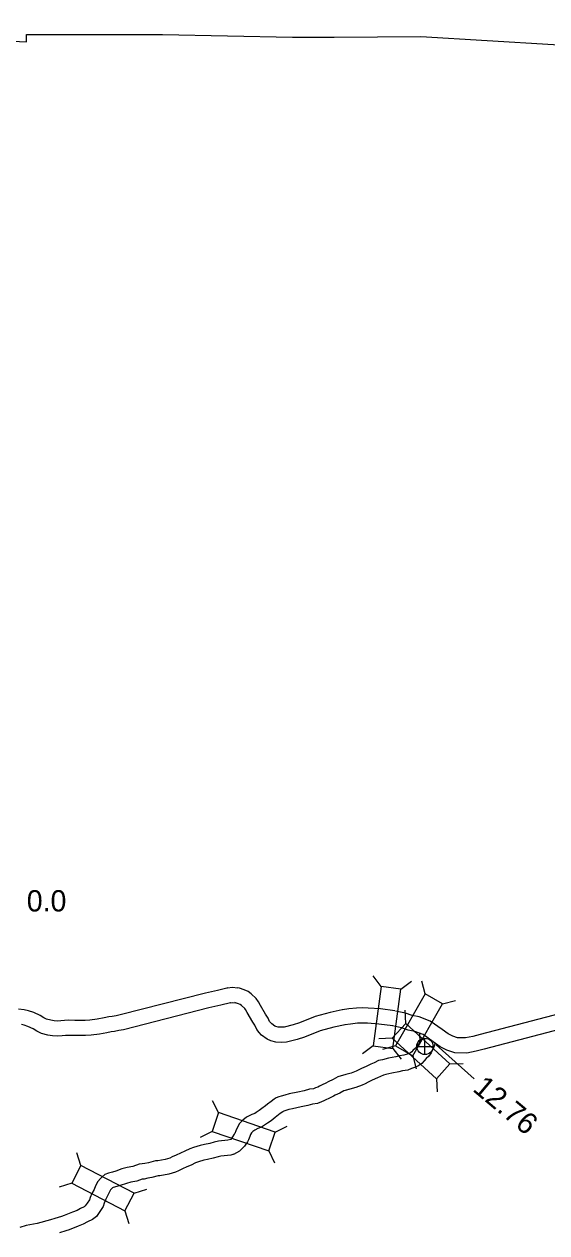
# Model space of a CAD drawing. Extents: x -939622 to -934245, y 1383184 to 1385301.
# Drawn here: x -936213.9 to -936182.8, y 1384317.3 to 1384389.2 of the extents above; entities that cross this region are included whole.
import ezdxf

# ---------------------------------------------------------------- set-up
doc = ezdxf.new("R2010")
doc.units = 0
for name, color, linetype in [('Level 10', 7, 'Continuous'), ('Level 2', 7, 'Continuous'), ('Level 20', 7, 'Continuous'), ('Level 25', 7, 'Continuous'), ('Level 26', 7, 'Continuous')]:
    doc.layers.add(name, color=color, linetype=linetype)

msp = doc.modelspace()

# ---------------------------------------------------------------- linework, layer by layer
at = {"layer": 'Level 10'}
for points in [[(-936201.82, 1384331.839), (-936201.866, 1384331.829), (-936202.427, 1384331.691), (-936203.146, 1384331.53), (-936208.214, 1384330.232), (-936208.445, 1384330.188), (-936208.692, 1384330.145), (-936208.889, 1384330.116), (-936209.171, 1384330.064), (-936209.59, 1384329.988), (-936210.023, 1384329.925), (-936210.302, 1384329.914), (-936210.655, 1384329.913), (-936210.918, 1384329.911), (-936211.259, 1384329.919), (-936211.527, 1384329.913), (-936211.743, 1384329.892), (-936211.968, 1384329.874), (-936212.138, 1384329.886), (-936212.332, 1384329.919), (-936212.587, 1384329.984), (-936212.75, 1384330.062), (-936212.971, 1384330.195), (-936213.357, 1384330.377), (-936213.662, 1384330.482), (-936213.922, 1384330.545), (-936214.261, 1384330.585)], [(-936201.82, 1384331.839), (-936201.532, 1384331.88), (-936201.237, 1384331.853)], [(-936195.013, 1384330.53), (-936195.714, 1384330.382), (-936196.608, 1384330.141), (-936197.556, 1384329.766), (-936197.931, 1384329.642), (-936198.454, 1384329.509), (-936198.619, 1384329.499), (-936198.815, 1384329.512), (-936198.962, 1384329.546), (-936199.01, 1384329.568), (-936199.2, 1384329.704), (-936199.259, 1384329.773), (-936199.322, 1384329.851), (-936199.418, 1384330.05), (-936199.561, 1384330.281), (-936199.873, 1384330.795), (-936199.977, 1384331.022), (-936200.126, 1384331.219), (-936200.425, 1384331.492), (-936200.603, 1384331.628), (-936200.836, 1384331.737), (-936201.121, 1384331.828), (-936201.237, 1384331.853)], [(-936174.729, 1384332.074), (-936175.041, 1384332.067), (-936175.524, 1384331.953), (-936176.172, 1384331.815), (-936176.86, 1384331.672), (-936186.804, 1384329.07), (-936187.241, 1384328.949), (-936187.674, 1384328.871), (-936188.153, 1384328.877), (-936188.428, 1384328.975), (-936188.71, 1384329.113), (-936189.068, 1384329.373), (-936189.778, 1384329.874), (-936190.439, 1384330.113), (-936190.842, 1384330.192), (-936191.235, 1384330.339), (-936191.835, 1384330.468)], [(-936201.638, 1384330.957), (-936201.659, 1384330.953), (-936202.221, 1384330.815), (-936202.936, 1384330.654), (-936208.017, 1384329.354), (-936208.283, 1384329.303), (-936208.549, 1384329.256), (-936208.741, 1384329.228), (-936209.009, 1384329.178), (-936209.445, 1384329.1), (-936209.939, 1384329.028), (-936210.283, 1384329.014), (-936210.649, 1384329.013), (-936210.925, 1384329.011), (-936211.26, 1384329.019), (-936211.472, 1384329.014), (-936211.663, 1384328.995), (-936211.964, 1384328.972), (-936212.244, 1384328.991), (-936212.519, 1384329.037), (-936212.894, 1384329.134), (-936213.177, 1384329.268), (-936213.396, 1384329.4), (-936213.697, 1384329.542), (-936213.915, 1384329.617), (-936214.081, 1384329.658)], [(-936201.674, 1384330.951), (-936201.509, 1384330.974), (-936201.346, 1384330.96)], [(-936194.826, 1384329.65), (-936195.503, 1384329.506), (-936196.324, 1384329.285), (-936197.249, 1384328.919), (-936197.679, 1384328.777), (-936198.315, 1384328.616), (-936198.623, 1384328.597), (-936198.948, 1384328.62), (-936199.252, 1384328.689), (-936199.463, 1384328.785), (-936199.811, 1384329.034), (-936199.951, 1384329.197), (-936200.089, 1384329.369), (-936200.208, 1384329.618), (-936200.328, 1384329.811), (-936200.668, 1384330.371), (-936200.754, 1384330.557), (-936200.794, 1384330.61), (-936201.003, 1384330.801), (-936201.073, 1384330.854), (-936201.165, 1384330.898), (-936201.355, 1384330.958), (-936201.402, 1384330.968)], [(-936174.707, 1384331.175), (-936174.925, 1384331.169), (-936175.326, 1384331.075), (-936175.987, 1384330.934), (-936176.655, 1384330.796), (-936186.57, 1384328.201), (-936187.041, 1384328.071), (-936187.6, 1384327.969), (-936188.313, 1384327.979), (-936188.778, 1384328.144), (-936189.177, 1384328.34), (-936189.592, 1384328.641), (-936190.198, 1384329.069), (-936190.68, 1384329.243), (-936191.088, 1384329.323), (-936191.489, 1384329.473), (-936192.025, 1384329.589)], [(-936191.87, 1384330.475), (-936192.729, 1384330.59), (-936193.457, 1384330.643), (-936193.771, 1384330.653), (-936194.163, 1384330.635), (-936194.616, 1384330.589), (-936194.984, 1384330.536)], [(-936191.989, 1384329.583), (-936192.822, 1384329.694), (-936193.503, 1384329.744), (-936193.764, 1384329.752), (-936194.097, 1384329.737), (-936194.505, 1384329.696), (-936194.855, 1384329.645)], [(-936190.415, 1384329.159), (-936190.417, 1384329.121), (-936190.41, 1384328.954), (-936190.384, 1384328.811), (-936190.371, 1384328.749), (-936190.371, 1384328.735), (-936190.391, 1384328.673), (-936190.434, 1384328.56), (-936190.487, 1384328.469), (-936190.559, 1384328.362), (-936190.655, 1384328.268), (-936190.796, 1384328.117), (-936190.863, 1384328.042), (-936190.951, 1384327.984), (-936191.033, 1384327.947), (-936191.193, 1384327.89), (-936191.34, 1384327.834), (-936191.596, 1384327.796), (-936191.823, 1384327.737), (-936192.25, 1384327.66), (-936192.618, 1384327.567), (-936192.839, 1384327.521), (-936193.114, 1384327.393), (-936193.3, 1384327.304), (-936193.587, 1384327.17), (-936193.858, 1384327.055), (-936194.06, 1384326.943), (-936194.175, 1384326.889), (-936194.48, 1384326.771), (-936194.789, 1384326.689), (-936194.985, 1384326.635)], [(-936189.482, 1384328.563), (-936189.54, 1384328.378), (-936189.619, 1384328.171), (-936189.724, 1384327.99), (-936189.864, 1384327.782), (-936190.011, 1384327.639), (-936190.131, 1384327.51), (-936190.271, 1384327.355), (-936190.516, 1384327.192), (-936190.697, 1384327.112), (-936190.882, 1384327.045), (-936191.111, 1384326.958), (-936191.417, 1384326.912), (-936191.632, 1384326.857), (-936192.06, 1384326.78), (-936192.414, 1384326.691), (-936192.553, 1384326.661), (-936192.73, 1384326.579), (-936192.914, 1384326.49), (-936193.222, 1384326.347), (-936193.464, 1384326.245), (-936193.649, 1384326.142), (-936193.819, 1384326.062), (-936194.201, 1384325.913), (-936194.555, 1384325.82), (-936194.747, 1384325.767)], [(-936194.795, 1384326.687), (-936195.266, 1384326.553), (-936195.552, 1384326.39), (-936195.847, 1384326.266), (-936195.979, 1384326.182), (-936196.197, 1384326.069), (-936196.35, 1384325.996), (-936196.459, 1384325.948), (-936196.595, 1384325.891), (-936196.71, 1384325.843), (-936196.952, 1384325.811), (-936197.261, 1384325.728), (-936197.642, 1384325.643), (-936198.162, 1384325.537), (-936198.423, 1384325.471), (-936198.635, 1384325.402), (-936198.771, 1384325.359), (-936198.939, 1384325.298), (-936199.054, 1384325.216), (-936199.23, 1384325.096), (-936199.459, 1384324.92), (-936199.567, 1384324.831), (-936199.778, 1384324.661), (-936199.951, 1384324.542), (-936200.115, 1384324.429), (-936200.211, 1384324.369), (-936200.377, 1384324.307), (-936200.692, 1384324.154), (-936200.917, 1384323.978), (-936201.122, 1384323.768), (-936201.279, 1384323.484), (-936201.33, 1384323.335), (-936201.399, 1384323.191), (-936201.424, 1384323.137), (-936201.637, 1384322.831)], [(-936194.549, 1384325.821), (-936194.914, 1384325.717), (-936195.152, 1384325.581), (-936195.43, 1384325.465), (-936195.53, 1384325.402), (-936195.794, 1384325.264), (-936195.975, 1384325.177), (-936196.104, 1384325.121), (-936196.248, 1384325.06), (-936196.474, 1384324.967), (-936196.775, 1384324.927), (-936197.046, 1384324.854), (-936197.454, 1384324.763), (-936197.962, 1384324.659), (-936198.173, 1384324.606), (-936198.361, 1384324.545), (-936198.481, 1384324.507), (-936198.516, 1384324.495), (-936198.538, 1384324.479), (-936198.701, 1384324.367), (-936198.899, 1384324.215), (-936198.999, 1384324.133), (-936199.24, 1384323.938), (-936199.441, 1384323.8), (-936199.622, 1384323.676), (-936199.811, 1384323.558), (-936200.021, 1384323.479), (-936200.213, 1384323.386), (-936200.315, 1384323.306), (-936200.393, 1384323.226), (-936200.453, 1384323.117), (-936200.495, 1384322.995), (-936200.585, 1384322.807), (-936200.642, 1384322.685), (-936200.826, 1384322.421)], [(-936201.637, 1384322.831), (-936201.811, 1384322.779), (-936202.363, 1384322.718), (-936202.616, 1384322.666), (-936202.888, 1384322.583), (-936203.202, 1384322.526), (-936203.463, 1384322.47), (-936203.844, 1384322.349), (-936204.079, 1384322.264), (-936204.37, 1384322.126), (-936204.627, 1384322.013), (-936204.887, 1384321.892), (-936205.114, 1384321.791), (-936205.262, 1384321.723), (-936205.529, 1384321.631), (-936205.972, 1384321.56), (-936206.105, 1384321.548), (-936206.527, 1384321.448), (-936206.752, 1384321.401), (-936206.902, 1384321.37), (-936207.079, 1384321.357), (-936207.46, 1384321.227), (-936207.787, 1384321.16), (-936208.104, 1384321.072), (-936208.476, 1384320.952), (-936208.678, 1384320.89), (-936208.913, 1384320.817), (-936209.116, 1384320.746), (-936209.307, 1384320.582), (-936209.387, 1384320.514), (-936209.538, 1384320.331), (-936209.674, 1384320.07), (-936209.768, 1384319.861), (-936209.898, 1384319.609), (-936209.995, 1384319.371), (-936210.044, 1384319.241), (-936210.167, 1384319.038), (-936210.288, 1384318.874), (-936210.347, 1384318.824), (-936210.563, 1384318.723), (-936210.774, 1384318.608), (-936211.049, 1384318.51), (-936211.546, 1384318.297), (-936211.708, 1384318.25), (-936212.089, 1384318.127), (-936212.363, 1384318.041), (-936213.152, 1384317.835), (-936213.797, 1384317.716), (-936214.179, 1384317.601)], [(-936201.462, 1384321.944), (-936201.087, 1384322.148), (-936200.826, 1384322.421)], [(-936201.462, 1384321.944), (-936201.631, 1384321.894), (-936202.222, 1384321.829), (-936202.394, 1384321.793), (-936202.677, 1384321.707), (-936203.026, 1384321.643), (-936203.231, 1384321.599), (-936203.555, 1384321.496), (-936203.732, 1384321.433), (-936203.995, 1384321.307), (-936204.257, 1384321.192), (-936204.515, 1384321.073), (-936204.742, 1384320.971), (-936204.927, 1384320.886), (-936205.31, 1384320.755), (-936205.86, 1384320.666), (-936205.961, 1384320.657), (-936206.333, 1384320.569), (-936206.568, 1384320.52), (-936206.777, 1384320.476), (-936206.899, 1384320.468), (-936207.223, 1384320.356), (-936207.577, 1384320.284), (-936207.846, 1384320.21), (-936208.207, 1384320.094), (-936208.411, 1384320.031), (-936208.63, 1384319.962), (-936208.66, 1384319.952), (-936208.724, 1384319.897), (-936208.744, 1384319.88), (-936208.783, 1384319.833), (-936208.864, 1384319.677), (-936208.957, 1384319.47), (-936209.079, 1384319.232), (-936209.157, 1384319.043), (-936209.231, 1384318.846), (-936209.419, 1384318.536), (-936209.628, 1384318.253), (-936209.86, 1384318.059), (-936210.156, 1384317.92), (-936210.404, 1384317.784), (-936210.72, 1384317.672), (-936211.242, 1384317.448), (-936211.445, 1384317.389), (-936211.816, 1384317.27)]]:
    msp.add_lwpolyline(points, dxfattribs=at)
at = {"layer": 'Level 2'}
for points in [[(-936251.651, 1384389.164), (-936245.181, 1384388.984), (-936237.26, 1384388.754), (-936229.485, 1384388.558), (-936221.642, 1384388.485), (-936213.787, 1384388.119), (-936213.776, 1384388.554), (-936205.7, 1384388.555), (-936197.96, 1384388.385), (-936195.486, 1384388.386)], [(-936195.486, 1384388.386), (-936190.324, 1384388.43), (-936182.44, 1384387.952), (-936174.485, 1384387.734), (-936166.726, 1384387.64), (-936158.459, 1384387.656), (-936150.405, 1384387.676), (-936142.667, 1384387.653), (-936139.352, 1384387.615)]]:
    msp.add_lwpolyline(points, dxfattribs=at)
at = {"layer": 'Level 20'}
for p, q in [((-936192.69, 1384331.928), (-936193.171, 1384332.558)), ((-936191.512, 1384331.771), (-936190.883, 1384332.251)), ((-936190.069, 1384331.481), (-936190.275, 1384332.246)), ((-936189.039, 1384330.889), (-936188.274, 1384331.096)), ((-936191.226, 1384329.724), (-936191.262, 1384330.516)), ((-936192.028, 1384328.847), (-936192.819, 1384328.812)), ((-936193.163, 1384328.396), (-936193.793, 1384327.915)), ((-936191.844, 1384328.391), (-936192.609, 1384328.184)), ((-936191.986, 1384328.238), (-936191.505, 1384327.609)), ((-936190.814, 1384327.799), (-936190.608, 1384327.034)), ((-936188.596, 1384327.32), (-936187.805, 1384327.355)), ((-936189.397, 1384326.443), (-936189.362, 1384325.652)), ((-936202.366, 1384324.423), (-936202.714, 1384325.134)), ((-936202.75, 1384323.299), (-936203.462, 1384322.95)), ((-936198.994, 1384323.269), (-936198.283, 1384323.617)), ((-936210.543, 1384321.285), (-936210.781, 1384322.04)), ((-936199.378, 1384322.145), (-936199.03, 1384321.434)), ((-936211.092, 1384320.231), (-936211.847, 1384319.993)), ((-936207.382, 1384319.639), (-936206.627, 1384319.877)), ((-936207.931, 1384318.585), (-936207.693, 1384317.83))]:
    msp.add_line(p, q, dxfattribs=at)
for points in [[(-936192.69, 1384331.928), (-936193.163, 1384328.396), (-936191.986, 1384328.238), (-936191.512, 1384331.771)], [(-936190.814, 1384327.799), (-936189.039, 1384330.889), (-936190.069, 1384331.481), (-936191.844, 1384328.391)], [(-936188.596, 1384327.32), (-936191.226, 1384329.724), (-936192.028, 1384328.847), (-936189.397, 1384326.443)], [(-936202.75, 1384323.299), (-936199.378, 1384322.145), (-936198.994, 1384323.269), (-936202.366, 1384324.423)], [(-936207.382, 1384319.639), (-936210.543, 1384321.285), (-936211.092, 1384320.231), (-936207.931, 1384318.585)]]:
    msp.add_lwpolyline(points, close=True, dxfattribs=at)
at = {"layer": 'Level 25'}
msp.add_line((-936189.414, 1384328.453), (-936187.15, 1384326.43), dxfattribs=at)
at = {"layer": 'Level 26'}
for p, q in [((-936190.086, 1384327.878), (-936190.086, 1384328.853)), ((-936190.573, 1384328.365), (-936189.598, 1384328.365))]:
    msp.add_line(p, q, dxfattribs=at)
msp.add_circle((-936190.086, 1384328.365), 0.487, dxfattribs=at)

# ---------------------------------------------------------------- texts
at = {"layer": 'Level 25'}
msp.add_text('0.0', height=1.2672, dxfattribs=at).set_placement((-936213.767, 1384336.389))
msp.add_text('12.76', height=1.2672, rotation=320, dxfattribs=at).set_placement((-936187.305, 1384325.754))

doc.saveas('drawing.dxf')
